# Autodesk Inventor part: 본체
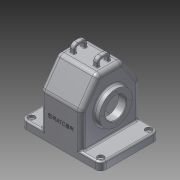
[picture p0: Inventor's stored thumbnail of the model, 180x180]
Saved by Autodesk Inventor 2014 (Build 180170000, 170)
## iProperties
Created: 2016-12
Part Number: 본체
Material: 알루미늄 6061
Document SubType Name: Modeling
Designer: USER
Density: 2.71 g/cm^3
Appearance: 알루미늄 - 평지
Mass: 1066.82 g
Surface Area: 1137.8 cm^2
Volume: 393.66 cm^3
Author: USER
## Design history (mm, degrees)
sketch "스케치1"
  geometry: L1 (0, 0)-(0, 139.451); L2 (0, 0)-(117.62, 0); L3 (0, 125)-(23.491, 125); L4 (23.491, 125)-(55, 80); L5 (55, 80)-(55, 0); L6 (55, 0)-(0, 0); L7 (0, 125)-(0, 0); L8 (0, 125)-(-23.491, 125); L9 (-23.491, 125)-(-55, 80); L10 (-55, 80)-(-55, 0); L11 (-55, 0)-(0, 0)
  constraints: 22 end point, 4 perpendicular, 3 symmetric about line, 2 point on line, 1 parallel, 1 vertical
  dimensions: "d0" = 80 distance of L4.end L5.end; "d1" = 35 deg angle of L4 L5; "d2" = 125 distance from line of L3 L5.end; "d3" = 110 diameter of L5 L1
extrude "돌출1" new body sketch "스케치1" stored distance "d4" = 77; taper "d5" = 0 deg
sketch "스케치2"
  geometry: L1 (55, 75)-(-55, 75); L2 (-55, 75)-(-55, -75); L3 (-55, -75)-(55, -75); L4 (55, -75)-(55, 75); L5 (0, 0)-(0, -86.258); L6 (0, 0)-(77.282, 0)
  constraints: 12 end point, 3 parallel, 2 perpendicular, 1 horizontal
  dimensions: "d6" = 150 diameter of L3 L6; "d7" = 110 diameter of L4 L5; "d8" = 110 distance between parallel lines of L4 L2; "d9" = 150 distance between parallel lines of L3 L1
extrude "돌출2" join sketch "스케치2" distance "d10" = 15; taper "d11" = 0 deg
sketch "스케치3"
  geometry: L1 (96, -38.5)-(65, -38.5); L2 (65, -38.5)-(65, -48.5); L3 (65, -48.5)-(96, -48.5); L4 (96, -48.5)-(96, -38.5); L5 (102.5, 43.5)-(65, 43.5); L6 (65, 43.5)-(65, 38.5); L7 (65, 38.5)-(102.5, 38.5); L8 (102.5, 38.5)-(102.5, 43.5); L9 (0, 0)-(165.185, 0); L10 (125, 38.5)-(80, 38.5) reference; L11 (80, -38.5)-(125, -38.5) reference; L12 (65, 46.962)-(65, -81.692); L13 (0, -75)-(0, 75) reference
  constraints: 20 end point, 4 parallel, 4 perpendicular, 3 point on line, 2 horizontal, 1 midpoint
  dimensions: "d12" = 5 distance between parallel lines of L5 L10; "d13" = 65 distance between parallel lines of L12 L13; "d14" = 62 diameter of L4 L12; "d15" = 87 distance between parallel lines of L3 L10; "d16" = 75 diameter of L8 L12
revolve "회전1" stored, may be unused: angle "d17" = 90 deg
revolve "회전2" stored, may be unused: angle "d18" = 90 deg
node "작업 평면1"
sketch "스케치4"
  geometry: L1 (55, 0)-(-55, 0) reference; L2 (-23.491, 125)-(23.491, 125) reference; L3 (0, 125)-(0, 155.963); L4 (12.5, 125)-(12.5, 132); L5 (7.5, 125)-(7.5, 132); L6 (-12.5, 125)-(-12.5, 132); L7 (-7.5, 125)-(-7.5, 132); L8 (-12.5, 125)-(-7.5, 125); L9 (7.5, 125)-(12.5, 125); L10 (4.5, 135)-(-4.5, 135); L11 (4.5, 140)-(-4.5, 140); A1 r 8 centre (4.5, 132) between (12.5, 132) and (4.5, 140); A2 r 8 centre (-4.5, 132) between (-4.5, 140) and (-12.5, 132); A3 r 3 centre (4.5, 132) between (7.5, 132) and (4.5, 135); A4 r 3 centre (-4.5, 132) between (-4.5, 135) and (-7.5, 132); 3 further points
  constraints: 18 end point, 8 point on circle, 6 symmetric about line, 5 tangent, 4 centre point, 4 parallel, 2 coincident, 2 collinear, 1 midpoint, 1 perpendicular, 1 point on line, 1 other
  dimensions: "d20" = 8 radius of A1; "d22" = 15 diameter of L5 L3; "d23" = 25 diameter of L4 L3; "d85" = 5 distance between parallel lines of L11 L10; "d86" = 140 distance between parallel lines of L1 L11
sketch "스케치5"
  geometry: L1 (27.5, 43.5)-(102.5, 43.5) reference; L2 (34, -48.5)-(96, -48.5) reference; L3 (65, 43.5)-(65, -48.5); L4 (65, 43.5)-(85, 43.5); L5 (85, 43.5)-(85, -48.5); L6 (85, -48.5)-(65, -48.5); L7 (65, -48.5)-(65, 43.5); 1 further point
  constraints: 10 end point, 2 midpoint, 2 parallel, 1 horizontal, 1 perpendicular, 1 point on line
  dimensions: "d28" = 40 diameter of L5 L3
revolve "회전3" sketch "스케치5" stored, may be unused: angle "d29" = 90 deg
sketch "스케치6"
  geometry: 1 further point
sketch "스케치7"
  geometry: L1 (55, 15)-(-55, 15) reference; L2 (-55, 15)-(-55, 80) reference; L3 (-55, 80)-(-23.491, 125) reference; L4 (-23.491, 125)-(23.491, 125) reference; L5 (23.491, 125)-(55, 80) reference; L6 (55, 80)-(55, 15) reference; L7 (50, 78.424)-(20.888, 120); L8 (20.888, 120)-(-20.888, 120); L9 (-20.888, 120)-(-50, 78.424); L10 (-50, 78.424)-(-50, 0); L11 (50, 0)-(50, 78.424); L12 (55, 0)-(-55, 0) reference; L13 (-50, 0)-(50, 0); C1 r 31 at (0, 65) reference; 1 further point
  constraints: 12 end point, 2 point on line, 1 collinear, 1 perpendicular, 3 other
  dimensions: "d30" = 5 distance between parallel lines of L3 L9; "d31" = 5 distance between parallel lines of L6 L11
extrude "돌출4" cut sketch "스케치7" stored distance "d32" = 67; taper "d33" = 0 deg
sketch "스케치10"
  geometry: 1 further point
sketch "스케치11"
  geometry: C1 r 31 at (0, 65) reference; C2 r 31 at (0, 65); 1 further point
  constraints: 1 centre point, 1 coincident, 1 concentric
extrude "돌출5" cut sketch "스케치11" stored distance "d34" = 10; taper "d35" = 0 deg
sketch "스케치12"
  geometry: L1 (45, 43.5)-(85, 43.5) reference; L2 (85, -48.5)-(45, -48.5) reference; L3 (65, 43.5)-(65, -48.5); L4 (85, 33.5)-(85, 43.5) reference; L5 (85, 33.5)-(106, 33.5); L6 (106, 33.5)-(92, 19.5); L7 (92, 19.5)-(85, 19.5); L8 (85, 19.5)-(85, 33.5); 1 further point
  constraints: 10 end point, 2 midpoint, 2 perpendicular, 1 parallel
  dimensions: "d36" = 54 diameter of L6.end L3; "d37" = 45 deg angle of L7 L6; "d38" = 24 distance between parallel lines of L7 L1
revolve "회전4" sketch "스케치12" stored, may be unused: angle "d39" = 90 deg
fillet "모깎기1" dims "d46" = 10
sketch "스케치14"
  geometry: L1 (45, 75)-(-45, 75) reference; L2 (55, 65)-(55, -65) reference; L3 (-45, -75)-(45, -75) reference; L4 (-55, 65)-(-55, -65) reference; L5 (50, 33.5)-(-50, 33.5) reference; L6 (-50, 33.5)-(-50, -33.5) reference; L7 (-50, -33.5)-(50, -33.5) reference; L8 (50, -33.5)-(50, 33.5) reference; A1 r 10 centre (-45, 65) between (-45, 75) and (-55, 65) reference; A2 r 10 centre (45, 65) between (55, 65) and (45, 75) reference; A3 r 10 centre (45, -65) between (45, -75) and (55, -65) reference; A4 r 10 centre (-45, -65) between (-55, -65) and (-45, -75) reference; 5 further points
  constraints: 4 coincident
hole "구멍1" sketch "스케치14" at (-45, -65), (45, -65), (45, 65), (-45, 65) diameter "d47" = 5; stored, may be unused: countersink angle "d51" = 90 deg, drill point angle "d53" = 118 deg; dims "d48" = 6, "d49" = 12, "d50" = 5, "d52" = 8
sketch "스케치15" dims "d54" = 52
  geometry: L1 (0, 0)-(0, 42.256); C1 r 31 at (0, 0) reference; 2 further points
  constraints: 2 end point, 1 coincident, 1 point on line, 1 vertical, 1 vertical alignment, 2 other
hole "구멍2" sketch "스케치15" at (0, 26) diameter "d55" = 2.459; stored, may be unused: countersink angle "d59" = 90 deg, drill point angle "d61" = 118 deg; dims "d56" = 6, "d57" = 12, "d58" = 5, "d60" = 8
sketch "스케치16" dims "d65" = 58
  geometry: L1 (0, 0)-(0, 34.84); C1 r 37.5 at (0, 0) reference; 2 further points
  constraints: 2 end point, 1 coincident, 1 point on line, 1 vertical, 1 vertical alignment, 2 other
hole "구멍3" sketch "스케치16" at (0, 29) diameter "d66" = 2.459; stored, may be unused: countersink angle "d70" = 90 deg, drill point angle "d72" = 118 deg; dims "d67" = 6, "d68" = 12, "d69" = 5, "d71" = 8
fillet "모깎기2" dims "d76" = 10
fillet "모깎기3" dims "d77" = 8
fillet "모깎기4" dims "d78" = 3
fillet "모깎기5" dims "d79" = 3
chamfer "모따기1" distance "d80" = 1; stored, may be unused: second distance "d81" = 2, angle "d82" = 45 deg
extrude "돌출6" join sketch "스케치4" distance "d87" = 8; taper "d88" = 0 deg
fillet "모깎기7" dims "d93" = 3
sketch "스케치18"
  geometry: L1 (18, 38.5)-(76.847, 38.5) reference; L2 (18, 0)-(76.847, 0); 2 further points
  constraints: 2 end point, 1 parallel, 1 point on line, 1 other
  dimensions: "d95" = 38.5 distance between parallel lines of L1 L2; "d96" = 45 distance of point (45, 0) point (0, 0)
feature "엠보싱1" sketch "스케치18" dims "d97" = 0.5, "d98" = 0
fillet "모깎기8" dims "d99" = 1
fillet "모깎기9" dims "d100" = 1
node "솔리드1"
pattern_circular "원형 패턴1" dims angle "d63" = 360 deg
pattern_circular "원형 패턴2" dims angle "d74" = 360 deg
mirror "대칭2"
mirror "대칭4"
node "투영된 루프1"
node "투영된 루프3"
other parameters: "d19" = -18, "d21" = 15
